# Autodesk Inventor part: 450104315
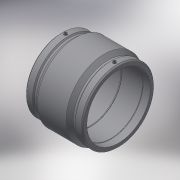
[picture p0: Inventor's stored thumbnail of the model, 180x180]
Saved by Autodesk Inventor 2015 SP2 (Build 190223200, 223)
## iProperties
Created: 2017-06
Part Number: 450104315
Material: Generic
Description: PLASSON COUPLER 315 PN25
Document SubType Name: Modeling
Designer: KIM
Mass: 8622.19 g
Surface Area: 6772.47 cm^2
Volume: 8622.19 cm^3
Density: 1 g/cm^3
Appearance: Default
Author: KIM
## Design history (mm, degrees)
derived "450104.ipt"
feature "Solid1::450104.ipt"
tag "TaggingFeature1"
body "Solid1"
other parameters: "d0" = 284, "d1" = 315, "d2" = 381, "d4" = 71, "d5" = 342.9, "d6" = 252, "d7" = 315, "d8" = 168 deg, "d10" = 56, "d11" = 18.66667, "d13" = 284, "d14" = 17.6296, "d17" = 311.85, "d18" = 315, "d19" = 3.52592, "d20" = 168 deg, "d22" = 358.14, "d23" = 381, "d24" = 347.3958, "d25" = 135 deg, "d26" = 142, "d27" = 135 deg, "d29" = 184, "d30" = 15, "d31" = 99.4, "d34" = 5 deg, "d35" = 15, "d39" = 5 deg, "d41" = 4, "d42" = 14, "d43" = 0, "d45" = 4, "d46" = 14, "d47" = 0, "d48" = 3, "d49" = 0, "d50" = 3, "d51" = 0, "d52" = 40.6, "d53" = 10.15, "d_" = 315, "L_" = 284, "D_" = 381, "A_" = 184, "d_2" = 12
